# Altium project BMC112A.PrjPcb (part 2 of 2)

## Sheet BMC112A_Power.SchDoc: LM5171 EVM Power Stage
size 431 x 279 mm; Date: Not shown in title block; ApprovedBy: Not shown in title block; CheckedBy: Not shown in title block; Author: Not shown in title block; CompanyName: Not shown in title block; Engineer: Not shown in title block; Organization: Not shown in title block; Address1: Not shown in title block; Address2: Not shown in title block; Address3: Not shown in title block; Address4: Not shown in title block; DocumentNumber: 3; Revision: Use project parameter SCH_Rev; SheetNumber: 6; SheetTotal: 8; PageSetup: Record=PageOptions¦CenterHorizontal=True¦CenterVertical=True¦PrintScale=1.00¦XCorrection=1.00¦YCorrection=1.00¦PrintKind=0¦BorderSize=5000000¦LeftOffset=0¦BottomOffset=0¦Orientation=2¦PaperLength=1000¦PaperWidth=1000¦Scale=100¦PaperSource=15¦PrintQuality=600¦MediaType=1¦DitherType=10¦PaperKind=Letter¦PrintScaleMode=1
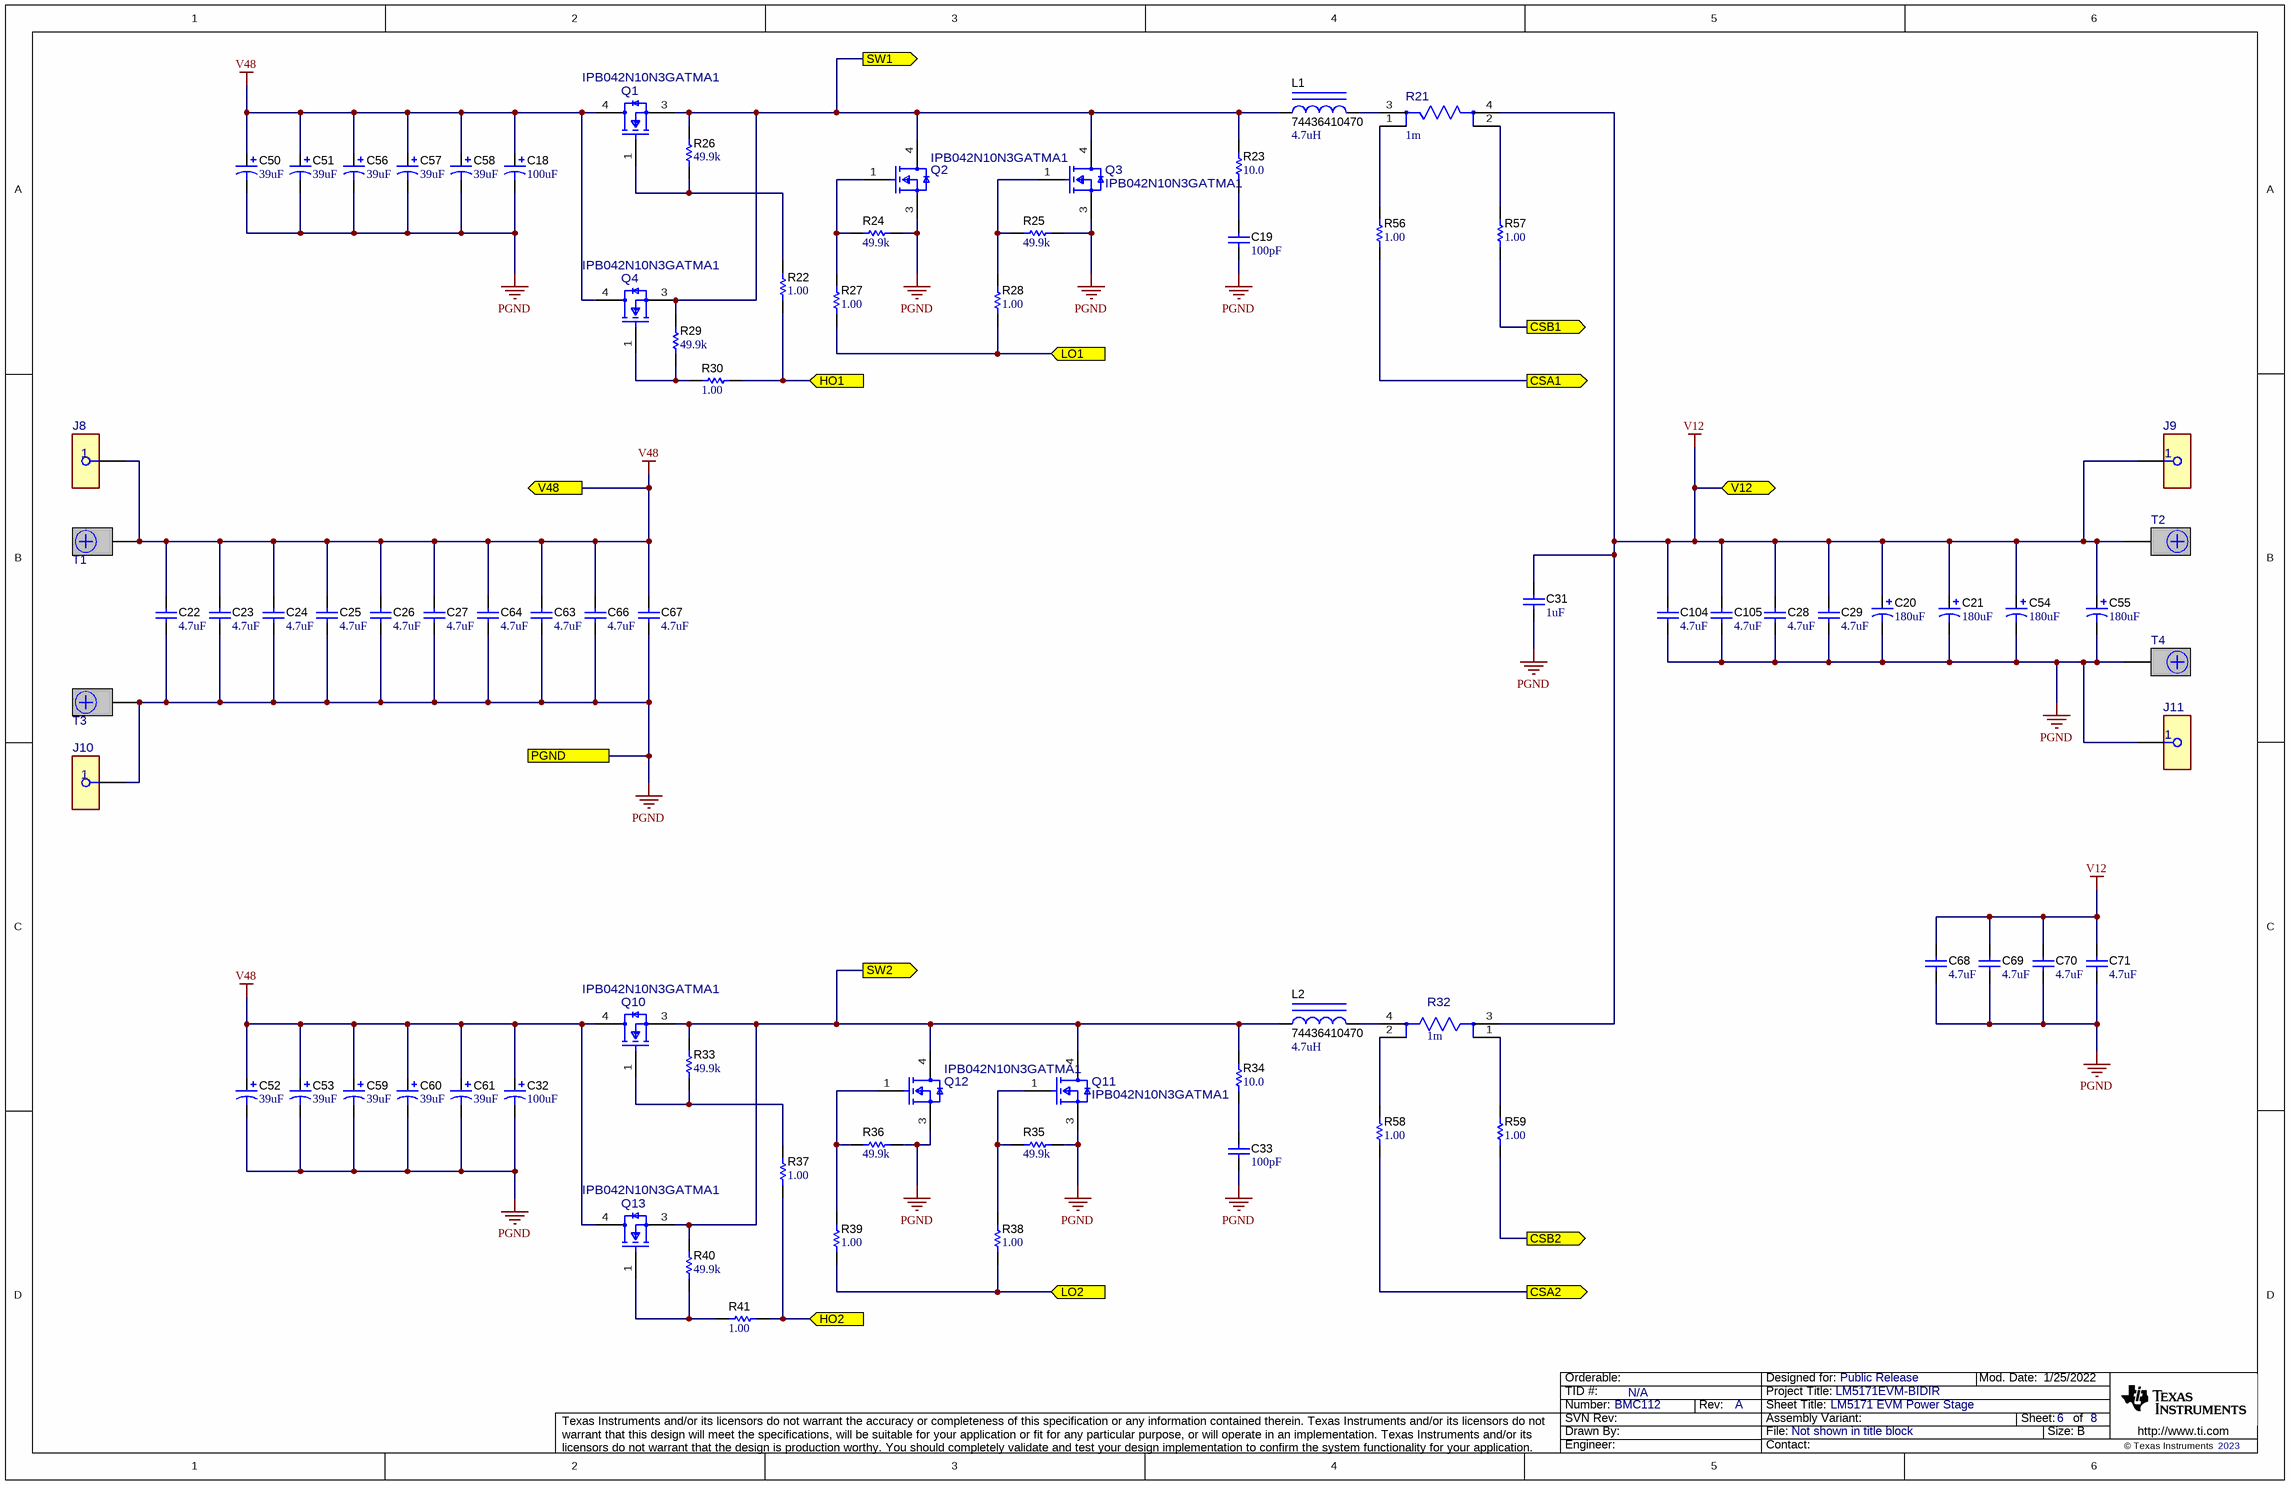
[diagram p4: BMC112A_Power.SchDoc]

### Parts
C18  ValueDisplayed: 100uF  [CAPSMT_62_LH0]  (hidden comment: EMVH101GDA101MLH0S)
C19  ValueDisplayed: 100pF  [0805L]  (hidden comment: 08051A101KAT2A)
C20  ValueDisplayed: 180uF  [CR_1000x1270]  (hidden comment: PCR1H181MCL1GS)
C21  ValueDisplayed: 180uF  [CR_1000x1270]  (hidden comment: PCR1H181MCL1GS)
C22  ValueDisplayed: 4.7uF  [2220_280]  (hidden comment: C5750X7R2A475M230KA)
C23  ValueDisplayed: 4.7uF  [2220_280]  (hidden comment: C5750X7R2A475M230KA)
C24  ValueDisplayed: 4.7uF  [2220_280]  (hidden comment: C5750X7R2A475M230KA)
C25  ValueDisplayed: 4.7uF  [2220_280]  (hidden comment: C5750X7R2A475M230KA)
C26  ValueDisplayed: 4.7uF  [2220_280]  (hidden comment: C5750X7R2A475M230KA)
C27  ValueDisplayed: 4.7uF  [2220_280]  (hidden comment: C5750X7R2A475M230KA)
C28  ValueDisplayed: 4.7uF  [2220_280]  (hidden comment: C5750X7R2A475M230KA)
C29  ValueDisplayed: 4.7uF  [2220_280]  (hidden comment: C5750X7R2A475M230KA)
C31  ValueDisplayed: 1uF  [1206_180]  (hidden comment: GRM31CR72A105KA01L)
C32  ValueDisplayed: 100uF  [CAPSMT_62_LH0]  (hidden comment: EMVH101GDA101MLH0S)
C33  ValueDisplayed: 100pF  [0805L]  (hidden comment: 08051A101KAT2A)
C50  ValueDisplayed: 39uF  [HXA_JA0]  (hidden comment: HHXA800ARA390MJA0G)
C51  ValueDisplayed: 39uF  [HXA_JA0]  (hidden comment: HHXA800ARA390MJA0G)
C52  ValueDisplayed: 39uF  [HXA_JA0]  (hidden comment: HHXA800ARA390MJA0G)
C53  ValueDisplayed: 39uF  [HXA_JA0]  (hidden comment: HHXA800ARA390MJA0G)
C54  ValueDisplayed: 180uF  [CR_1000x1270]  (hidden comment: PCR1H181MCL1GS)
C55  ValueDisplayed: 180uF  [CR_1000x1270]  (hidden comment: PCR1H181MCL1GS)
C56  ValueDisplayed: 39uF  [HXA_JA0]  (hidden comment: HHXA800ARA390MJA0G)
C57  ValueDisplayed: 39uF  [HXA_JA0]  (hidden comment: HHXA800ARA390MJA0G)
C58  ValueDisplayed: 39uF  [HXA_JA0]  (hidden comment: HHXA800ARA390MJA0G)
C59  ValueDisplayed: 39uF  [HXA_JA0]  (hidden comment: HHXA800ARA390MJA0G)
C60  ValueDisplayed: 39uF  [HXA_JA0]  (hidden comment: HHXA800ARA390MJA0G)
C61  ValueDisplayed: 39uF  [HXA_JA0]  (hidden comment: HHXA800ARA390MJA0G)
C63  ValueDisplayed: 4.7uF  [2220_280]  (hidden comment: C5750X7R2A475M230KA)
C64  ValueDisplayed: 4.7uF  [2220_280]  (hidden comment: C5750X7R2A475M230KA)
C66  ValueDisplayed: 4.7uF  [2220_280]  (hidden comment: C5750X7R2A475M230KA)
C67  ValueDisplayed: 4.7uF  [2220_280]  (hidden comment: C5750X7R2A475M230KA)
C68  ValueDisplayed: 4.7uF  [2220_280]  (hidden comment: C5750X7R2A475M230KA)
C69  ValueDisplayed: 4.7uF  [2220_280]  (hidden comment: C5750X7R2A475M230KA)
C70  ValueDisplayed: 4.7uF  [2220_280]  (hidden comment: C5750X7R2A475M230KA)
C71  ValueDisplayed: 4.7uF  [2220_280]  (hidden comment: C5750X7R2A475M230KA)
C104  ValueDisplayed: 4.7uF  [2220_280]  (hidden comment: C5750X7R2A475M230KA)
C105  ValueDisplayed: 4.7uF  [2220_280]  (hidden comment: C5750X7R2A475M230KA)
J8  6095  [FP-6095_CONN_JACK-MFG]  (value not drawn)
J9  6095  [FP-6095_CONN_JACK-MFG]  (value not drawn)
J10  6095  [FP-6095_CONN_JACK-MFG]  (value not drawn)
J11  6095  [FP-6095_CONN_JACK-MFG]  (value not drawn)
L1  74436410470  value 4.7uH  [WE-HCF_2818]
L2  74436410470  value 4.7uH  [WE-HCF_2818]
Q1  IPB042N10N3GATMA1  [FP-IPB042N10N3GATMA1_D2PAK-MFG]
Q2  IPB042N10N3GATMA1  [FP-IPB042N10N3GATMA1_D2PAK-MFG]
Q3  IPB042N10N3GATMA1  [FP-IPB042N10N3GATMA1_D2PAK-MFG]
Q4  IPB042N10N3GATMA1  [FP-IPB042N10N3GATMA1_D2PAK-MFG]
Q10  IPB042N10N3GATMA1  [FP-IPB042N10N3GATMA1_D2PAK-MFG]
Q11  IPB042N10N3GATMA1  [FP-IPB042N10N3GATMA1_D2PAK-MFG]
Q12  IPB042N10N3GATMA1  [FP-IPB042N10N3GATMA1_D2PAK-MFG]
Q13  IPB042N10N3GATMA1  [FP-IPB042N10N3GATMA1_D2PAK-MFG]
R21  value 1m  [FP-FC4L90R001GER_1835-MFG]  (hidden comment: FC4L90R001GER)
R22  ValueDisplayed: 1.00  [0805L]  (hidden comment: CRCW08051R00FKEA)
R23  ValueDisplayed: 10.0  [1218]  (hidden comment: CRCW121810R0FKEK)
R24  ValueDisplayed: 49.9k  [0805L]  (hidden comment: CRCW080549K9FKEA)
R25  ValueDisplayed: 49.9k  [0805L]  (hidden comment: CRCW080549K9FKEA)
R26  ValueDisplayed: 49.9k  [0805L]  (hidden comment: CRCW080549K9FKEA)
R27  ValueDisplayed: 1.00  [0805L]  (hidden comment: CRCW08051R00FKEA)
R28  ValueDisplayed: 1.00  [0805L]  (hidden comment: CRCW08051R00FKEA)
R29  ValueDisplayed: 49.9k  [0805L]  (hidden comment: CRCW080549K9FKEA)
R30  ValueDisplayed: 1.00  [0805L]  (hidden comment: CRCW08051R00FKEA)
R32  value 1m  [FP-FC4L90R001GER_1835-MFG]  (hidden comment: FC4L90R001GER)
R33  ValueDisplayed: 49.9k  [0805L]  (hidden comment: CRCW080549K9FKEA)
R34  ValueDisplayed: 10.0  [1218]  (hidden comment: CRCW121810R0FKEK)
R35  ValueDisplayed: 49.9k  [0805L]  (hidden comment: CRCW080549K9FKEA)
R36  ValueDisplayed: 49.9k  [0805L]  (hidden comment: CRCW080549K9FKEA)
R37  ValueDisplayed: 1.00  [0805L]  (hidden comment: CRCW08051R00FKEA)
R38  ValueDisplayed: 1.00  [0805L]  (hidden comment: CRCW08051R00FKEA)
R39  ValueDisplayed: 1.00  [0805L]  (hidden comment: CRCW08051R00FKEA)
R40  ValueDisplayed: 49.9k  [0805L]  (hidden comment: CRCW080549K9FKEA)
R41  ValueDisplayed: 1.00  [0805L]  (hidden comment: CRCW08051R00FKEA)
R56  ValueDisplayed: 1.00  [0603L]  (hidden comment: CRCW06031R00FKEA)
R57  ValueDisplayed: 1.00  [0603L]  (hidden comment: CRCW06031R00FKEA)
R58  ValueDisplayed: 1.00  [0603L]  (hidden comment: CRCW06031R00FKEA)
R59  ValueDisplayed: 1.00  [0603L]  (hidden comment: CRCW06031R00FKEA)
T1  CXS70-14-C  [Panduit_CXS70-14-C]  (value not drawn)
T2  CXS70-14-C  [Panduit_CXS70-14-C]  (value not drawn)
T3  CXS70-14-C  [Panduit_CXS70-14-C]  (value not drawn)
T4  CXS70-14-C  [Panduit_CXS70-14-C]  (value not drawn)

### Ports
CSA1 (out), CSA2 (out), CSB1 (out), CSB2 (out), HO1 (in), HO2 (in), LO1 (in), LO2 (in), PGND, SW1 (out), SW2 (out), V12 (bidir), V48 (out)

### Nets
PGND: C18.2(-) C19.2 C20.2(-) C21.2(-) C22.2 C23.2 C24.2 C25.2 C26.2 C27.2 C28.2 C29.2 C31.1 C32.2(-) C33.2 C50.2(-) C51.2(-) C52.2(-) C53.2(-) C54.2(-) C55.2(-) C56.2(-) C57.2(-) C58.2(-) C59.2(-) C60.2(-) C61.2(-) C63.2 C64.2 C66.2 C67.2 C68.2 C69.2 C70.2 C71.2 C104.2 C105.2 J10.1 J11.1 Q2.3(SOURCE) Q3.3(SOURCE) Q11.3(SOURCE) Q12.3(SOURCE) R24.2 R25.2 R35.2 R36.2 T3.1 T4.1 ; port PGND
V12: C20.1(+) C21.1(+) C28.1 C29.1 C31.2 C54.1(+) C55.1(+) C68.1 C69.1 C70.1 C71.1 C104.1 C105.1 J9.1 R21.4(2_I) R32.3(1_I) T2.1 ; port V12
V48: C18.1(+) C22.1 C23.1 C24.1 C25.1 C26.1 C27.1 C32.1(+) C50.1(+) C51.1(+) C52.1(+) C53.1(+) C56.1(+) C57.1(+) C58.1(+) C59.1(+) C60.1(+) C61.1(+) C63.1 C64.1 C66.1 C67.1 J8.1 Q1.4(DRAIN) Q4.4(DRAIN) Q10.4(DRAIN) Q13.4(DRAIN) T1.1 ; port V48
CSA1: R56.1 ; port CSA1
CSA2: R58.1 ; port CSA2
CSB1: R57.1 ; port CSB1
CSB2: R59.1 ; port CSB2
HO1: R22.1 R30.1 ; port HO1
HO2: R37.1 R41.1 ; port HO2
LO1: R27.1 R28.1 ; port LO1
LO2: R38.1 R39.1 ; port LO2
SW1: L1.1 Q1.3(SOURCE) Q2.4(DRAIN) Q3.4(DRAIN) Q4.3(SOURCE) R23.2 R26.1 R29.1 ; port SW1
SW2: L2.2 Q10.3(SOURCE) Q11.4(DRAIN) Q12.4(DRAIN) Q13.3(SOURCE) R33.2 R34.2 R40.2 ; port SW2
NetC19_1: C19.1 R23.1
NetC33_1: C33.1 R34.1
NetL1_2: L1.2 R21.3(1_I)
NetL2_1: L2.1 R32.4(2_I)
NetQ1_1: Q1.1(GATE) R22.2 R26.2
NetQ2_1: Q2.1(GATE) R24.1 R27.2
NetQ3_1: Q3.1(GATE) R25.1 R28.2
NetQ4_1: Q4.1(GATE) R29.2 R30.2
NetQ10_1: Q10.1(GATE) R33.1 R37.2
NetQ11_1: Q11.1(GATE) R35.1 R38.2
NetQ12_1: Q12.1(GATE) R36.1 R39.2
NetQ13_1: Q13.1(GATE) R40.1 R41.2
NetR21_1: R21.1(1_V) R56.2
NetR21_2: R21.2(2_V) R57.2
NetR32_1: R32.1(1_V) R59.2
NetR32_2: R32.2(2_V) R58.2

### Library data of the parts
C18 C32 = CMP-0011313-2: CAP, AL, 100 uF, 100 V, +/- 20%, 0.24 ohm, SMD; Manufacturer: Chemi-Con; Polarized: Y; CompType: Capacitor; Value: 100uF; U/M: EA; Cap_F: 100µF; VDC_V: 100V; ESR_ohm: 0.24; IRMS_A: 650mA; TaMin_C: -40°C; TaMax_C: 125°C; Cap_Case: LH0; AEC Category: Q200; SizeArea_mm2: 289; SizeAreaWB_mm2: 361; SizeX_mm: 17; SizeZ_mm: 16.5
C19 C33 = CMP-0007518-2: CAP, CERM, 100 pF, 100 V, +/- 10%, C0G/NP0, 0805; Manufacturer: AVX; Polarized: N; Value: 100pF; U/M: EA; ESR_ohm: 0.356; Value1: 0.356 ohm; VDC_V: 100V; TaMin_C: -55°C; TaMax_C: 125°C; Cap_Case: 0805; AEC Category: Q200; SizeArea_mm2: 2.5; SizeAreaWB_mm2: 6.75; SizeX_mm: 2; SizeY_mm: 1.25; SizeZ_mm: 1.45
C20 C21 C54 C55 = CMP-0012273-3: CAP, Aluminum Polymer, 180 uF, 50 V, +/- 20%, 0.019 ohm, SMD, 2-Leads, Dia 10.5mm, Pin Spacing 8mm SMD; Manufacturer: Nichicon; Polarized: Y; CompType: Capacitor; Value: 180uF; Cap_F: 180µF; VDC_V: 50V; ESR_ohm: 19m; IRMS_A: 3.5A; TaMin_C: -55°C; TaMax_C: 125°C; Cap_Case: 10x12.7mm; AEC Category: Q200; AEC Qualified: N
C22-C29 C63 C64 C66-C71 C104 C105 = CMP-0009385-2: CAP, CERM, 4.7 uF, 100 V, +/- 20%, X7R, 2220; Manufacturer: TDK; Polarized: N; Value: 4.7uF; U/M: EA; Cap_F: 4.7µF; ESR_ohm: 1.5m; Value1: 0.0015 ohm; VDC_V: 100V; IRMS_A: 5.5A; TaMin_C: -55°C; TaMax_C: 125°C; Cap_Case: 2220; AEC Category: Q200; SizeArea_mm2: 28.5; SizeAreaWB_mm2: 53.9; SizeX_mm: 5.7; SizeY_mm: 5; SizeZ_mm: 2.8
C31 = CMP-0008970-2: CAP, CERM, 1 uF, 100 V, +/- 10%, X7R, 1206; Manufacturer: MuRata; Polarized: N; Value: 1uF; U/M: EA; Cap_F: 1µF; Value1: Unknown; VDC_V: 100V; TaMin_C: -55°C; TaMax_C: 125°C; Cap_Case: 2220; SizeArea_mm2: 5.12; SizeAreaWB_mm2: 10.92; SizeX_mm: 3.2; SizeY_mm: 1.6; SizeZ_mm: 1.8; AEC Category: Q200
C50-C53 C56-C61 = CMP-0012265-3: CAP, Aluminum Polymer, 39 uF, 80 V, +/- 20%, 0.035 ohm, AEC-Q200 Grade 1, D10xL10mm SMD; Manufacturer: Chemi-Con; CompType: Capacitor; ESR_ohm: 35m; VDC_V: 80V; Value: 39uF; Polarized: Y; Cap_F: 39µF; IRMS_A: 1.2A; TaMin_C: -55°C; TaMax_C: 125°C; Cap_Case: 10X10mm; AEC Category: Q200; AEC Grade: 1
J8-J11 = CMP-0097398-1: Banana Jack Connector Standard Banana Solder Lug; Manufacturer: Keystone Electronics; AEC Qualified: No; ContactFinish: Tin; Is Female: yes; Conn Orientation: Vertical
L1 L2 = CMP-0064062-1: Inductor, Shielded, Ferrite, 4.7 uH, 32 A, 0.0015 ohm, SMD; Manufacturer: Wurth Elektronik; AEC Category: Q200; AEC Qualified: N; DCR_ohm: 1.5m; Green_Lifecycle: Not Set; Green_REACh: Incomplete; Imax_A: 32A; Ind_H: 4.7µH; Irms: 32A @ 50C rise; Isat: 45A @ 20% inductance drop; SizeArea_mm2: 555.75; SizeAreaWB_mm2: 655.75; SizeX_mm: 28.5; SizeY_mm: 19.5; SizeZ_mm: 18.5
Q1-Q4 Q10-Q13 = CMP-0087591-1: N-Channel 100V 100A (Tc) 214W (Tc) Surface Mount D²PAK (TO-263AB); Manufacturer: Infineon; Transconductance: 145S; Turn Off Delay Time: 48ns; IdsMax_A: 137A; TJmax_C: +175°C; Pulse Drain Current: 548A; Threshold Vgs Max: 3.5V; Rdson45_ohm: 3.6mΩ; Typ Forward Diode Voltage: 1V; Standoff Height: 0mm; QgTyp_nC: 88nC @ 10V; Reverse Recovery Time: 68ns; Import Ts: 1521842123; SizeZ_mm: 4.7mm; Input Capacitace At Vds: 6320pF @ 50V; Rthja Max: 62K/W; Threshold Vgs Min: 2V; Reverse Recovery Charge: 135nC; Number Of Channels: 1; Ciiva Ids: 4154385; ChMode: False; AEC Qualified: No; Max Forward Diode Voltage: 1.2V; Turn On Delay Time: 27ns; Vgs_V: 20V
R21 R32 = CMP-0001578-1: 1 mOhms ±2% 4W Chip Resistor Wide 3518 (9045 Metric), 1835 Current Sense, Moisture Resistant Metal Foil; Manufacturer: Ohmite; AEC Qualified: No; SizeZ_mm: 0.8mm; TempCo: 100ppm/°C
R22 R27 R28 R30 R37-R39 R41 = CMP-0021009-3: RES, 1.00, 1%, 0.125 W, AEC-Q200 Grade 0, 0805; Manufacturer: Vishay-Dale; Value: 1.00; Res_ohm: 1; Value_Code: 1R00; Power_W: 125mW; Value2: 0.125W; VDC_V: 150V; TempCo: 100 ppm/C; EIA_Code: E96; AEC Category: Q200; AEC Grade: 0; AEC Qualified: Y; SizeArea_mm2: 2.5; SizeX_mm: 2; SizeY_mm: 1.25; SizeZ_mm: 1.45
R23 R34 = CMP-0015024-3: RES, 10.0, 1%, 1 W, AEC-Q200 Grade 0, 1218; Manufacturer: Vishay-Dale; Value: 10.0; Res_ohm: 10; Value_Code: 10R0; Power_W: 1W; VDC_V: 200V; TempCo: 100 ppm/C; EIA_Code: E96; AEC Category: Q200; AEC Grade: 0; AEC Qualified: Y; SizeArea_mm2: 14.72; SizeAreaWB_mm2: 23.52; SizeX_mm: 3.2; SizeY_mm: 4.6; SizeZ_mm: 0.6
R24-R26 R29 R33 R35 R36 R40 = CMP-0021283-3: RES, 49.9 k, 1%, 0.125 W, AEC-Q200 Grade 0, 0805; Manufacturer: Vishay-Dale; Value: 49.9k; Value_Code: 49k9; Power_W: 125mW; Value2: 0.125W; VDC_V: 150V; TempCo: 100 ppm/C; EIA_Code: E96; AEC Category: Q200; AEC Grade: 0; AEC Qualified: Y; SizeArea_mm2: 2.5; SizeX_mm: 2; SizeY_mm: 1.25; SizeZ_mm: 1.45
R56-R59 = CMP-0022170-4: RES, 1.00, 1%, 0.1 W, AEC-Q200 Grade 0, 0603; Manufacturer: Vishay-Dale; Value: 1.00; Res_ohm: 1; Value_Code: 1R00; Power_W: 100mW; Value2: 0.1W; VDC_V: 75V; TempCo: 100 ppm/C; EIA_Code: E96; AEC Category: Q200; AEC Qualified: Y; AEC Grade: 0; SizeArea_mm2: 1.28; SizeX_mm: 1.6; SizeY_mm: 0.8
T1-T4 = CMP-0075010-2: Terminal 70A Lug; Manufacturer: Panduit; CompType: Screw Terminal; CNHeader: False; Green_Lifecycle: Not Set; Green_REACh: Incomplete

## Sheet BMC112A_Interface.SchDoc: LM5171 EVM Interface Schematic
size 431 x 279 mm; Date: Not shown in title block; ApprovedBy: Not shown in title block; CheckedBy: Not shown in title block; Author: Not shown in title block; CompanyName: Not shown in title block; Engineer: Not shown in title block; Organization: Not shown in title block; Address1: Not shown in title block; Address2: Not shown in title block; Address3: Not shown in title block; Address4: Not shown in title block; DocumentNumber: 4; Revision: Use project parameter SCH_Rev; SheetNumber: 7; SheetTotal: 8; PageSetup: Record=PageOptions¦CenterHorizontal=True¦CenterVertical=True¦PrintScale=1.00¦XCorrection=1.00¦YCorrection=1.00¦PrintKind=0¦BorderSize=5000000¦LeftOffset=0¦BottomOffset=0¦Orientation=2¦PaperLength=1000¦PaperWidth=1000¦Scale=100¦PaperSource=15¦PrintQuality=600¦MediaType=1¦DitherType=10¦PaperKind=Letter¦PrintScaleMode=1
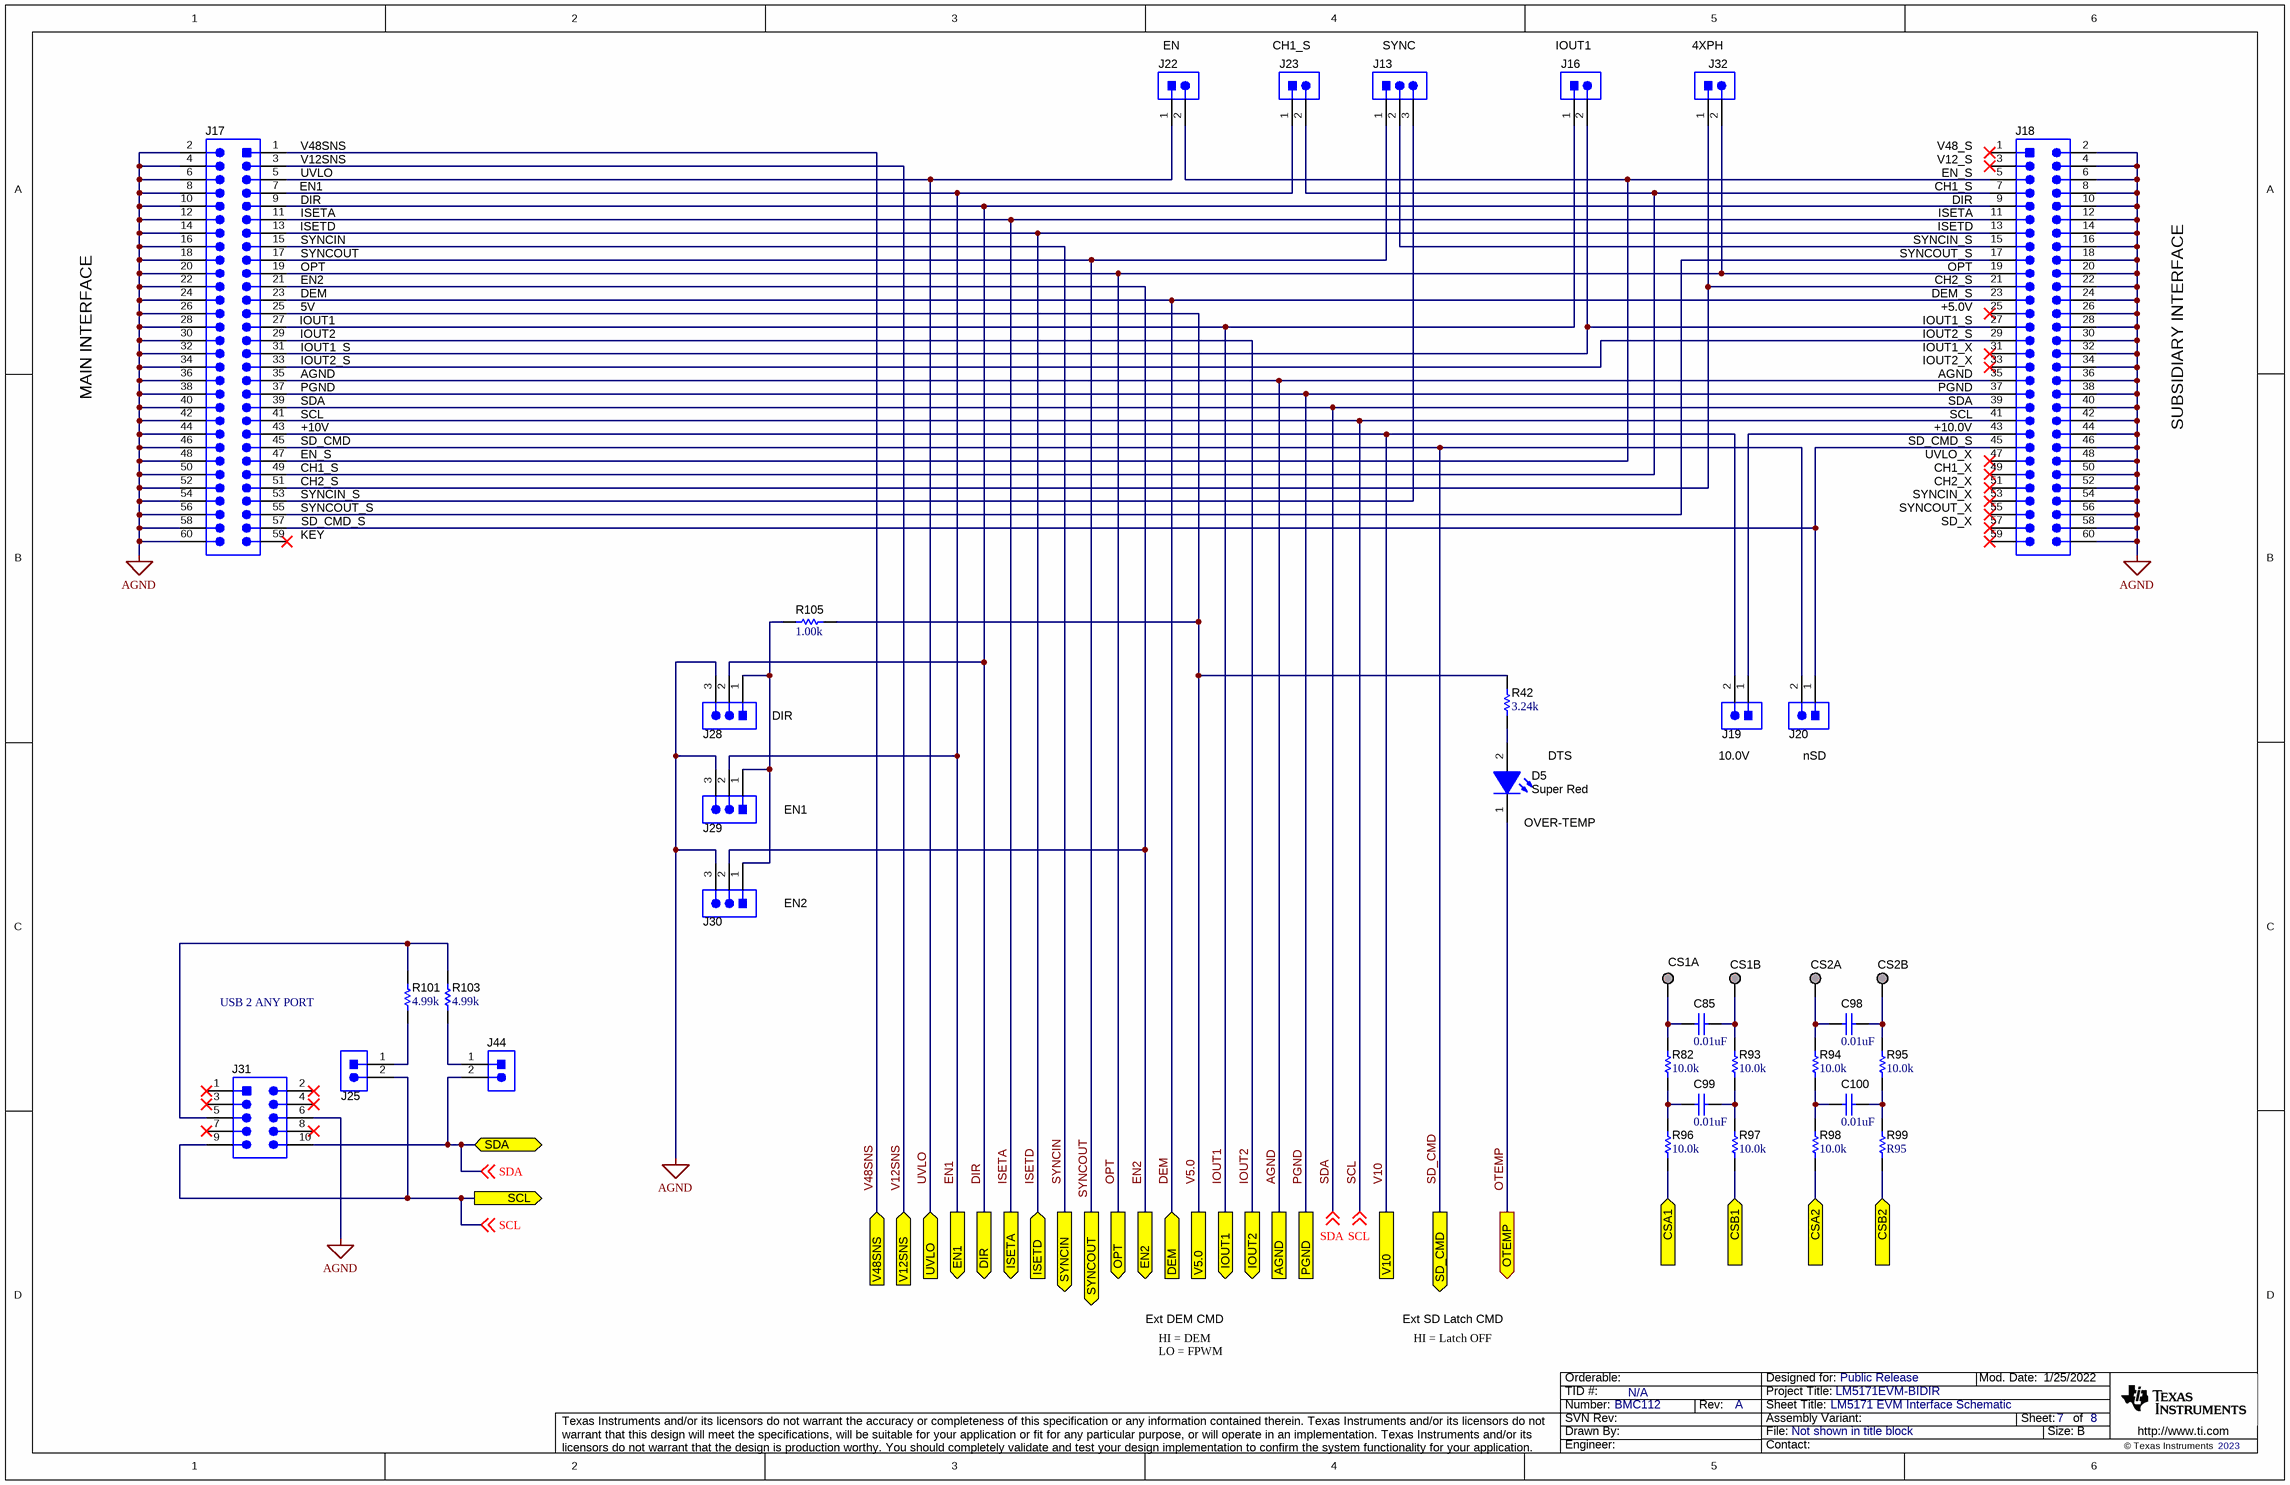
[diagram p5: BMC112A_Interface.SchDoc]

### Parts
C85  ValueDisplayed: 0.01uF  [0603L]  (hidden comment: 06031C103KAT2A)
C98  ValueDisplayed: 0.01uF  [0603L]  (hidden comment: 06031C103KAT2A)
C99  ValueDisplayed: 0.01uF  [0603L]  (hidden comment: 06031C103KAT2A)
C100  ValueDisplayed: 0.01uF  [0603L]  (hidden comment: 06031C103KAT2A)
CS1A  S2751-46R  [Harwin_S2751-46R]  (value not drawn)  (no BOM)
CS1B  S2751-46R  [Harwin_S2751-46R]  (value not drawn)  (no BOM)
CS2A  S2751-46R  [Harwin_S2751-46R]  (value not drawn)  (no BOM)
CS2B  S2751-46R  [Harwin_S2751-46R]  (value not drawn)  (no BOM)
D5  value Super Red  [WL-SMCW_RED]  (hidden comment: 150060SS75000)
J13  61300311121  [WURTH_61300311121]  (value not drawn)
J16  61300211121  [WURTH_61300211121]  (value not drawn)
J17  HMTSW-130-07-G-D-240  [SAMTEC_HMTSW-130-07-G-D-240]  (value not drawn)
J18  HMTSW-130-07-G-D-240  [SAMTEC_HMTSW-130-07-G-D-240]  (value not drawn)
J19  61300211121  [WURTH_61300211121]  (value not drawn)
J20  61300211121  [WURTH_61300211121]  (value not drawn)
J22  61300211121  [WURTH_61300211121]  (value not drawn)
J23  61300211121  [WURTH_61300211121]  (value not drawn)
J25  61300211121  [WURTH_61300211121]  (value not drawn)
J28  61300311121  [WURTH_61300311121]  (value not drawn)
J29  61300311121  [WURTH_61300311121]  (value not drawn)
J30  61300311121  [WURTH_61300311121]  (value not drawn)
J31  N2510-6002-RB  [CONN_2510-6002]  (value not drawn)
J32  61300211121  [WURTH_61300211121]  (value not drawn)
J44  61300211121  [WURTH_61300211121]  (value not drawn)
R42  ValueDisplayed: 3.24k  [0603L]  (hidden comment: CRCW06033K24FKEA)
R82  ValueDisplayed: 10.0k  [0603L]  (hidden comment: CRCW060310K0FKEA)
R93  ValueDisplayed: 10.0k  [0603L]  (hidden comment: CRCW060310K0FKEA)
R94  ValueDisplayed: 10.0k  [0603L]  (hidden comment: CRCW060310K0FKEA)
R95  ValueDisplayed: 10.0k  [0603L]  (hidden comment: CRCW060310K0FKEA)
R96  ValueDisplayed: 10.0k  [0603L]  (hidden comment: CRCW060310K0FKEA)
R97  ValueDisplayed: 10.0k  [0603L]  (hidden comment: CRCW060310K0FKEA)
R98  ValueDisplayed: 10.0k  [0603L]  (hidden comment: CRCW060310K0FKEA)
R99  ValueDisplayed: R95  [0603L]  (hidden comment: CRCW060310K0FKEA)
R101  ValueDisplayed: 4.99k  [0603]  (hidden comment: CRCW06034K99FKEAC)
R103  ValueDisplayed: 4.99k  [0603]  (hidden comment: CRCW06034K99FKEAC)
R105  ValueDisplayed: 1.00k  [0603]  (hidden comment: RC0603FR-071KL)

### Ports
AGND, CSA1 (in), CSA2 (in), CSB1 (in), CSB2 (in), DEM (in), DIR (out), EN1 (out), EN2 (out), IOUT1 (out), IOUT2 (out), ISETA (out), ISETD (in), OPT (out), OTEMP (out), PGND, SCL (out), SD_CMD (out), SDA (bidir), SYNCIN (out), SYNCOUT (out), UVLO (in), V5.0, V10, V12SNS (in), V48SNS (in)

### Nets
AGND: J17.2 J17.4 J17.6 J17.8 J17.10 J17.12 J17.14 J17.16 J17.18 J17.20 J17.22 J17.24 J17.26 J17.28 J17.30 J17.32 J17.34 J17.35 J17.36 J17.38 J17.40 J17.42 J17.44 J17.46 J17.48 J17.50 J17.52 J17.54 J17.56 J17.58 J17.60 J18.2 J18.4 J18.6 J18.8 J18.10 J18.12 J18.14 J18.16 J18.18 J18.20 J18.22 J18.24 J18.26 J18.28 J18.30 J18.32 J18.34 J18.35 J18.36 J18.38 J18.40 J18.42 J18.44 J18.46 J18.48 J18.50 J18.52 J18.54 J18.56 J18.58 J18.60 J28.3 J29.3 J30.3 J31.6 ; port AGND
PGND: J17.37 J18.37 ; port PGND
V5.0: J17.25 R42.2 R105.2 ; port V5.0
V10: J17.43 J19.2 ; port V10
CSA1: R96.1 ; port CSA1
CSA2: R98.1 ; port CSA2
CSB1: R97.1 ; port CSB1
CSB2: R99.1 ; port CSB2
DEM: J17.23 J18.23 ; port DEM
DIR: J17.9 J18.9 J28.2 ; port DIR
EN1: J17.7 J23.1 J29.2 ; port EN1
EN2: J17.21 J30.2 ; port EN2
IOUT1: J16.1 J17.27 ; port IOUT1
IOUT2: J17.29 ; port IOUT2
ISETA: J17.11 J18.11 ; port ISETA
ISETD: J17.13 J18.13 ; port ISETD
OPT: J17.19 J18.19 J32.2 ; port OPT
OTEMP: D5.1(K) ; port OTEMP
SCL: J17.41 J18.41 J25.2 J31.9 ; off-sheet SCL, port SCL
SD_CMD: J17.45 J20.2 ; port SD_CMD
SDA: J17.39 J18.39 J31.10 J44.2 ; off-sheet SDA, port SDA
SYNCIN: J17.15 ; port SYNCIN
SYNCOUT: J13.1 J17.17 ; port SYNCOUT
UVLO: J17.5 J22.1 ; port UVLO
V12SNS: J17.3 ; port V12SNS
V48SNS: J17.1 ; port V48SNS
NetC85_1: C85.1 CS1B.1 R93.2
NetC85_2: C85.2 CS1A.1 R82.2
NetC98_1: C98.1 CS2B.1 R95.2
NetC98_2: C98.2 CS2A.1 R94.2
NetC99_1: C99.1 R93.1 R97.2
NetC99_2: C99.2 R82.1 R96.2
NetC100_1: C100.1 R95.1 R99.2
NetC100_2: C100.2 R94.1 R98.2
NetD5_2: D5.2(A) R42.1
NetJ13_2: J13.2 J18.15
NetJ13_3: J13.3 J17.53
NetJ16_2: J16.2 J17.31 J18.27
NetJ17_33: J17.33 J18.29
NetJ17_47: J17.47 J18.5 J22.2
NetJ17_49: J17.49 J18.7 J23.2
NetJ17_51: J17.51 J18.21 J32.1
NetJ17_55: J17.55 J18.17
NetJ17_57: J17.57 J18.45 J20.1
NetJ18_43: J18.43 J19.1
NetJ25_1: J25.1 R101.1
NetJ28_1: J28.1 J29.1 J30.1 R105.1
NetJ31_5: J31.5 R101.2 R103.2
NetJ44_1: J44.1 R103.1

Not connected (* = marked no-connect by the designer): J17 59*; J18 1* 3* 25* 31* 33* 47* 49* 51* 53* 55* 57* 59*; J31 1* 2* 3* 4* 7* 8*

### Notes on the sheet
- (near J22) EN
- (near J23) CH1_S
- (near J13) SYNC
- (near J16) IOUT1
- (near J32) 4XPH
- (near J17) UVLO
- (near J17) V48SNS
- (near J17) V12SNS
- (near J18) V48_S
- (near J18) V12_S
- (near J18) EN_S
- (near J17) DIR
- (near J17) EN1
- (near J17) ISETA
- (near J17) ISETD
- (near J18) CH1_S
- (near J18) ISETD
- (near J18) ISETA
- (near J18) DIR
- (near J17) 5V
- (near J17) EN2
- (near J17) OPT
- (near J17) DEM
- (near J17) SYNCIN
- (near J17) SYNCOUT
- (near J18) SYNCOUT_S
- (near J18) SYNCIN_S
- (near J18) DEM_S
- (near J18) CH2_S
- (near J18) +5.0V
- (near J18) OPT
- MAIN INTERFACE
- (near J17) IOUT1
- (near J17) IOUT2
- (near J17) IOUT1_S
- (near J17) IOUT2_S
- (near J18) IOUT1_X
- (near J18) IOUT2_X
- (near J18) IOUT1_S
- (near J18) IOUT2_S
- SUBSIDIARY INTERFACE
- (near J17) SCL
- (near J17) SDA
- (near J17) +10V
- (near J17) AGND
- (near J17) PGND
- (near J17) SD_CMD
- (near J18) SD_CMD_S
- (near J18) +10.0V
- (near J18) AGND
- (near J18) PGND
- (near J18) SDA
- (near J18) SCL
- (near J17) EN_S
- (near J17) CH1_S
- (near J17) CH2_S
- (near J17) SYNCIN_S
- (near J18) SYNCIN_X
- (near J18) UVLO_X
- (near J18) CH1_X
- (near J18) CH2_X
- (near J17) KEY
- (near J17) SD_CMD_S
- (near J17) SYNCOUT_S
- (near J18) SYNCOUT_X
- (near J18) SD_X
- (near J28) DIR
- DTS
- 10.0V
- (near J20) nSD
- (near J29) EN1
- (near D5) OVER-TEMP
- (near J30) EN2
- USB 2 ANY PORT
- HI = DEM   LO = FPWM
- Ext DEM CMD
- HI = Latch OFF
- Ext SD Latch CMD

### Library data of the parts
C85 C98-C100 = CMP-0006727-4: CAP, CERM, 0.01 uF, 100 V, +/- 10%, X7R, 0603; Manufacturer: AVX; Polarized: N; Value: 0.01uF; U/M: EA; Cap_F: 10nF; ESR_ohm: 98m; Value1: 0.098 ohm; VDC_V: 100V; TaMin_C: -55°C; TaMax_C: 125°C; Cap_Case: 0603; AEC Category: Q200; SizeArea_mm2: 1.28; SizeAreaWB_mm2: 4.68; SizeX_mm: 1.6; SizeY_mm: 0.8; SizeZ_mm: 1
CS1A CS1B CS2A CS2B = CMP-0003968-1: Test Point, SMT; Manufacturer: Harwin
D5 = CMP-0002893-1: LED, Super Red, SMD; Manufacturer: Wurth Elektronik; Type: AlInGaP; Vf_V: 1.9V; Io_A: 20mA; Value1: W; U/M: EA
J13 = CMP-0054796-4: Header, 2.54 mm, 3x1, Gold, TH; Manufacturer: Wurth Elektronik; Green_Lifecycle: Active; Green_REACh: Passed; CT: FALSE; CNHeader: TRUE
J16 J19 J20 J22 J23 J32 = CMP-0054794-2: Header, 2.54 mm, 2x1, Gold, TH; Manufacturer: Wurth Elektronik; Cert_UL: Y; Gender: Male; Green_Lifecycle: Active; Green_REACh: Passed; Pitch_mm: 2.54; Row_Count: 1; Shrouded: N
J17 J18 = CMP-0075499-1: Header, 100mil, 30x2, Gold, TH; Manufacturer: Samtec; CNHeader: True; CT: False; Green_Lifecycle: Active; Green_REACh: Passed
J25 J44 = CMP-0054794-2: Header, 2.54 mm, 2x1, Gold, TH; Manufacturer: Wurth Elektronik; Shrouded: N; Gender: Male; Green_REACh: Passed; Pitch_mm: 2.54; Green_Lifecycle: Active; Row_Count: 1; Cert_UL: Y
J28-J30 = CMP-0054796-4: Header, 2.54 mm, 3x1, Gold, TH; Manufacturer: Wurth Elektronik; Green_Lifecycle: Active; Green_REACh: Passed; CNHeader: TRUE; CT: FALSE
J31 = CMP-0055448-2: Header (shrouded), 100mil, 5x2, High-Temperature, Gold, TH; Manufacturer: 3M; Green_Lifecycle: Active; Green_REACh: Passed
R42 = CMP-0022374-4: RES, 3.24 k, 1%, 0.1 W, AEC-Q200 Grade 0, 0603; Manufacturer: Vishay-Dale; Value: 3.24k; Value_Code: 3k24; Power_W: 100mW; Value2: 0.1W; VDC_V: 75V; TempCo: 100 ppm/C; EIA_Code: E96; AEC Category: Q200; AEC Grade: 0; AEC Qualified: Y; SizeArea_mm2: 1.28; SizeX_mm: 1.6; SizeY_mm: 0.8; SizeZ_mm: 1
R82 R93-R99 = CMP-0021998-4: RES, 10.0 k, 1%, 0.1 W, AEC-Q200 Grade 0, 0603; Manufacturer: Vishay-Dale; Value: 10.0k; Res_ohm: 10k; Value_Code: 10k0; Power_W: 100mW; Value2: 0.1W; VDC_V: 75V; TempCo: 100 ppm/C; EIA_Code: E96; AEC Category: Q200; AEC Qualified: Y; AEC Grade: 0; SizeArea_mm2: 1.28; SizeX_mm: 1.6; SizeY_mm: 0.8; SizeZ_mm: 1
R101 R103 = CMP-0082533-1: RES, 4.99 k, 1%, 0.1 W, 0603; Manufacturer: Vishay-Dale; Power_W: 100mW; TempCo: 100 ppm/C; SizeAreaWB_mm2: 4.68; Value_Code: 4k99; Value: 4.99k; EIA_Code: E96; SizeX_mm: 1.6; SizeY_mm: 0.8; SizeZ_mm: 1; Value2: 0.1W; SizeArea_mm2: 1.28; AEC Qualified: N; VDC_V: 75V; AEC Category: Q200
R105 = CMP-0022895-5: RES, 1.00 k, 1%, 0.1 W, 0603; Manufacturer: Yageo; Power_W: 100mW; TempCo: 100 ppm/C; Value_Code: 1k00; Value: 1.00k; EIA_Code: E96; Res_ohm: 1k; SizeX_mm: 1.6; SizeY_mm: 0.8; SizeZ_mm: 1; Value2: 0.1W; SizeArea_mm2: 1.28; AEC Qualified: N; VDC_V: 75V; AEC Category: Q200; SizeAreaWB_mm2: 4.68

## Sheet BMC112A_Analog.SchDoc: LM5171 EVM Analog Control
size 431 x 279 mm; Date: Not shown in title block; ApprovedBy: Not shown in title block; CheckedBy: Not shown in title block; Author: Not shown in title block; CompanyName: Not shown in title block; Engineer: Not shown in title block; Organization: Not shown in title block; Address1: Not shown in title block; Address2: Not shown in title block; Address3: Not shown in title block; Address4: Not shown in title block; DocumentNumber: 2; Revision: Use project parameter SCH_Rev; SheetNumber: 4; SheetTotal: 8; PageSetup: Record=PageOptions¦CenterHorizontal=True¦CenterVertical=True¦PrintScale=1.00¦XCorrection=1.00¦YCorrection=1.00¦PrintKind=0¦BorderSize=5000000¦LeftOffset=0¦BottomOffset=0¦Orientation=2¦PaperLength=1000¦PaperWidth=1000¦Scale=100¦PaperSource=15¦PrintQuality=600¦MediaType=1¦DitherType=10¦PaperKind=Letter¦PrintScaleMode=1
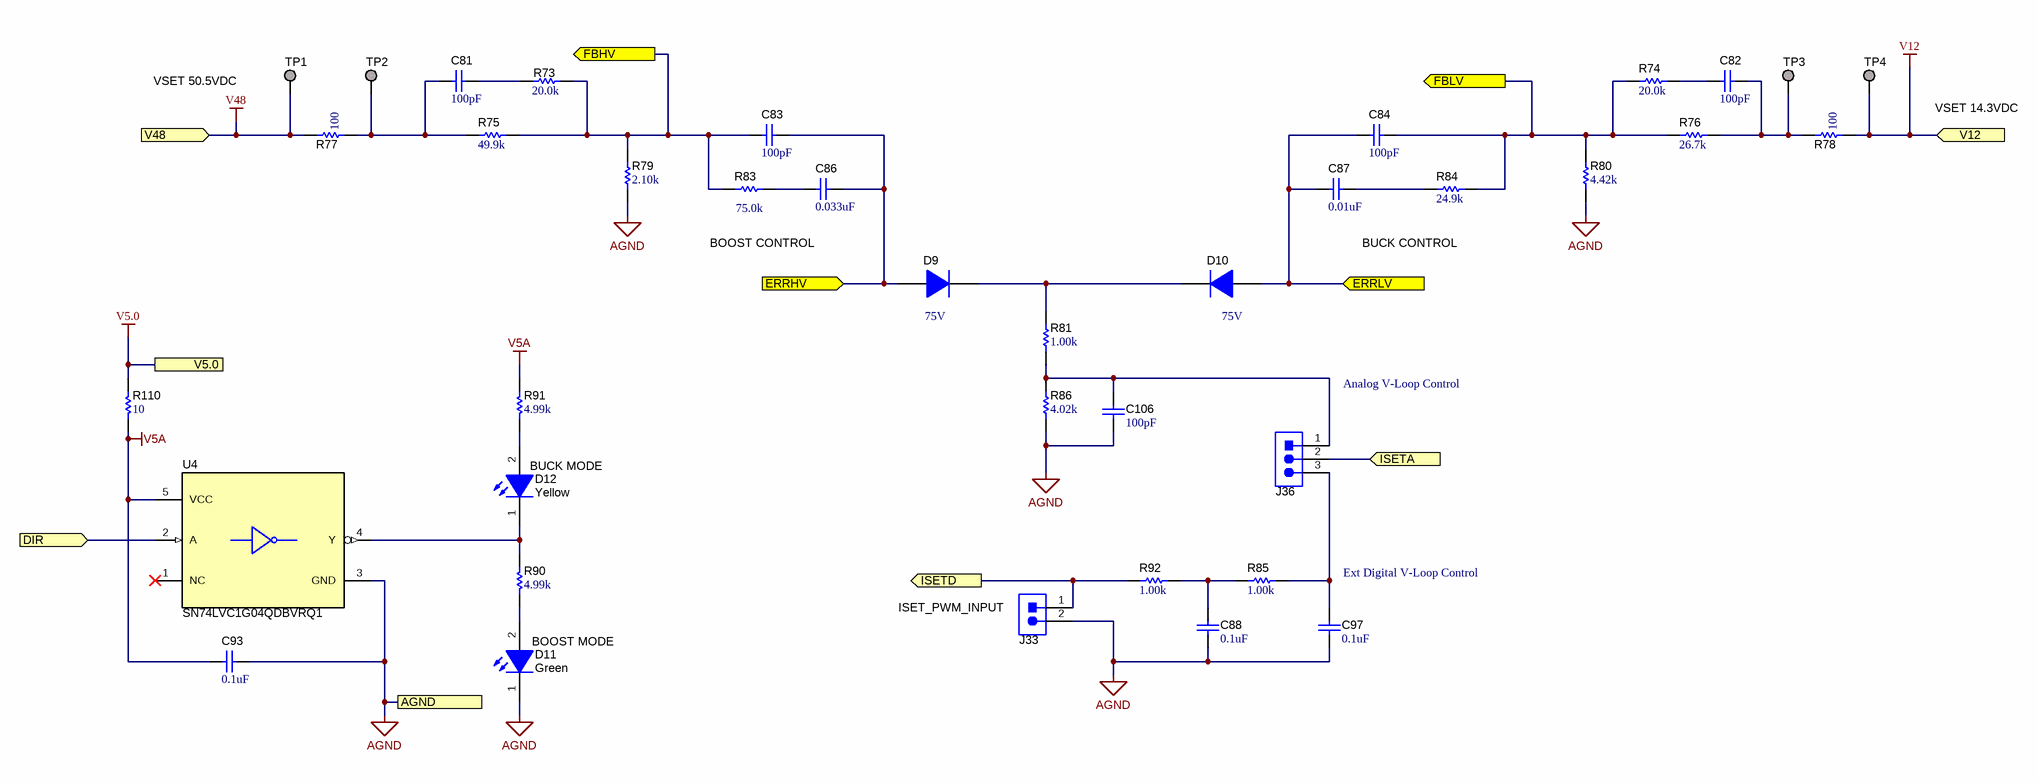
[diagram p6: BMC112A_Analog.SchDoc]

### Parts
C81  ValueDisplayed: 100pF  [0603L]  (hidden comment: C0603C101J5GACTU)
C82  ValueDisplayed: 100pF  [0603L]  (hidden comment: C0603C101J5GACTU)
C83  ValueDisplayed: 100pF  [0603L]  (hidden comment: C0603C101J5GACTU)
C84  ValueDisplayed: 100pF  [0603L]  (hidden comment: C0603C101J5GACTU)
C86  ValueDisplayed: 0.033uF  [0603L]  (hidden comment: CGA3E3X7S2A333K080AB)
C87  ValueDisplayed: 0.01uF  [0603L]  (hidden comment: 06031C103KAT2A)
C88  ValueDisplayed: 0.1uF  [0603L]  (hidden comment: GRM188R72A104KA35D)
C93  ValueDisplayed: 0.1uF  [0603L]  (hidden comment: GRM188R72A104KA35D)
C97  ValueDisplayed: 0.1uF  [0603L]  (hidden comment: GRM188R72A104KA35D)
C106  ValueDisplayed: 100pF  [0603L]  (hidden comment: C0603C101J5GACTU)
D9  value 75V  [SOD-323]  (hidden comment: 1N4448WX-TP)
D10  value 75V  [SOD-323]  (hidden comment: 1N4448WX-TP)
D11  value Green  [WL-SMCW_GREEN]  (hidden comment: 150060VS75000)
D12  value Yellow  [WL-SMCW_YELLOW]  (hidden comment: 150060YS75000)
J33  61300211121  [WURTH_61300211121]  (value not drawn)
J36  61300311121  [WURTH_61300311121]  (value not drawn)
R73  ValueDisplayed: 20.0k  [0603L]  (hidden comment: CRCW060320K0FKEA)
R74  ValueDisplayed: 20.0k  [0603L]  (hidden comment: CRCW060320K0FKEA)
R75  ValueDisplayed: 49.9k  [0805L]  (hidden comment: CRCW080549K9FKEA)
R76  ValueDisplayed: 26.7k  [0805L]  (hidden comment: CRCW080526K7FKEA)
R77  ValueDisplayed: 100  [0603L]  (hidden comment: CRCW0603100RFKEA)
R78  ValueDisplayed: 100  [0603L]  (hidden comment: CRCW0603100RFKEA)
R79  ValueDisplayed: 2.10k  [0603L]  (hidden comment: CRCW06032K10FKEA)
R80  ValueDisplayed: 4.42k  [0603L]  (hidden comment: CRCW06034K42FKEA)
R81  ValueDisplayed: 1.00k  [0603L]  (hidden comment: CRCW06031K00FKEA)
R83  ValueDisplayed: 75.0k  [0603L]  (hidden comment: RC0603FR-0775KL)
R84  ValueDisplayed: 24.9k  [0603L]  (hidden comment: CRCW060324K9FKEA)
R85  ValueDisplayed: 1.00k  [0603L]  (hidden comment: CRCW06031K00FKEA)
R86  ValueDisplayed: 4.02k  [0603L]  (hidden comment: CRCW06034K02FKEA)
R90  ValueDisplayed: 4.99k  [0603L]  (hidden comment: CRCW06034K99FKEA)
R91  ValueDisplayed: 4.99k  [0603L]  (hidden comment: CRCW06034K99FKEA)
R92  ValueDisplayed: 1.00k  [0603L]  (hidden comment: CRCW06031K00FKEA)
R110  ValueDisplayed: 10  [0805_HV1]  (hidden comment: CRCW080510R0JNEA)
TP1  S2761-46R  [Harwin_S2761-46R]  (value not drawn)
TP2  S2761-46R  [Harwin_S2761-46R]  (value not drawn)
TP3  S2761-46R  [Harwin_S2761-46R]  (value not drawn)
TP4  S2761-46R  [Harwin_S2761-46R]  (value not drawn)
U4  SN74LVC1G04QDBVRQ1  [DBV0005A_N]

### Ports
AGND, DIR (in), ERRHV (in), ERRLV (in), FBHV (out), FBLV (out), ISETA (in), ISETD (out), V5.0, V12 (in), V48 (in)

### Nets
AGND: C88.2 C93.1 C97.2 C106.2 D11.1(K) J33.2 R79.2 R80.2 R86.1 U4.3(GND) ; port AGND
V5.0: R110.2 ; port V5.0
V5A: C93.2 R91.1 R110.1 U4.5(VCC)
V12: R78.1 TP4.1 ; port V12
V48: R77.2 TP1.1 ; port V48
DIR: U4.2(A) ; port DIR
ERRHV: C83.1 C86.1 D9.2(A) ; port ERRHV
ERRLV: C84.2 C87.1 D10.2(A) ; port ERRLV
FBHV: C83.2 R73.1 R75.1 R79.1 R83.2 ; port FBHV
FBLV: C84.1 R74.2 R76.2 R80.1 R84.2 ; port FBLV
ISETA: J36.2 ; port ISETA
ISETD: J33.1 R92.1 ; port ISETD
NetC81_1: C81.1 R73.2
NetC81_2: C81.2 R75.2 R77.1 TP2.1
NetC82_1: C82.1 R76.1 R78.2 TP3.1
NetC82_2: C82.2 R74.1
NetC86_2: C86.2 R83.1
NetC87_2: C87.2 R84.1
NetC88_1: C88.1 R85.1 R92.2
NetC97_1: C97.1 J36.3 R85.2
NetC106_1: C106.1 J36.1 R81.1 R86.2
NetD9_1: D9.1(K) D10.1(K) R81.2
NetD11_2: D11.2(A) R90.2
NetD12_1: D12.1(K) R90.1 U4.4(Y)
NetD12_2: D12.2(A) R91.2

Not connected (* = marked no-connect by the designer): U4 1(NC)*

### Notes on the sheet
- VSET 50.5VDC
- VSET 14.3VDC
- BOOST CONTROL
- BUCK CONTROL
- Analog V-Loop Control
- (near D12) BUCK MODE
- (near D11) BOOST MODE
- (near J33) ISET_PWM_INPUT
- Ext Digital V-Loop Control

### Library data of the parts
C81-C84 C106 = CMP-0006841-4: CAP, CERM, 100 pF, 50 V, +/- 5%, C0G/NP0, 0603; Manufacturer: Kemet; Polarized: N; Value: 100pF; U/M: EA; Value1: Unknown; VDC_V: 50V; TaMin_C: -55°C; TaMax_C: 125°C; Cap_Case: 0603; AEC Category: Q200; SizeArea_mm2: 1.28; SizeAreaWB_mm2: 4.68; SizeX_mm: 1.6; SizeY_mm: 0.8; SizeZ_mm: 1
C86 = CMP-0007100-4: CAP, CERM, 0.033 uF, 100 V, +/- 10%, X7S, AEC-Q200 Grade 1, 0603; Manufacturer: TDK; Polarized: N; U/M: EA; Cap_F: 33nF; ESR_ohm: 0.1396; Value1: 0.139637 ohm; VDC_V: 100V; IRMS_A: 462.257mA; TaMin_C: -55°C; TaMax_C: 125°C; Cap_Case: 0603; AEC Category: Q200; AEC Qualified: Y; AEC Grade: 1; SizeArea_mm2: 1.28; SizeAreaWB_mm2: 4.68; SizeX_mm: 1.6; SizeY_mm: 0.8
C87 = CMP-0006727-4: as C85 on sheet BMC112A_Interface
C88 C93 C97 = CMP-0007469-4: CAP, CERM, 0.1 uF, 100 V, +/- 10%, X7R, 0603; Manufacturer: MuRata; Polarized: N; Value: 0.1uF; U/M: EA; Cap_F: 100nF; Value1: Unknown; VDC_V: 100V; TaMin_C: -55°C; TaMax_C: 125°C; Cap_Case: 0603; AEC Category: Q200; SizeArea_mm2: 1.28; SizeAreaWB_mm2: 4.68; SizeX_mm: 1.6; SizeY_mm: 0.8; SizeZ_mm: 1
D9 D10 = CMP-0076911-2: Diode, Switching, 75 V, 0.25 A, SOD-323; Manufacturer: Micro Commercial Components; Value1: 0.25A; Io_A: 250mA; TJmax_C: 150°C; AEC Category: Q101; Green_Lifecycle: Not Set; Green_REACh: Incomplete; SizeArea_mm2: 3.645; SizeAreaWB_mm2: 8.695; SizeX_mm: 2.7; SizeY_mm: 1.35; SizeZ_mm: 1.0
D11 = CMP-0002894-2: LED, Green, SMD; Manufacturer: Wurth Elektronik; Type: AlInGaP; Vf_V: 2V; Io_A: 20mA; Value1: W
D12 = CMP-0002892-3: LED, Yellow, SMD; Manufacturer: Wurth Elektronik; Type: AlInGaP; Vf_V: 2V; Io_A: 20mA; Value1: W
J33 = CMP-0054794-2: as J16 on sheet BMC112A_Interface
J36 = CMP-0054796-4: as J28-J30 on sheet BMC112A_Interface
R73 R74 = CMP-0022204-4: RES, 20.0 k, 1%, 0.1 W, AEC-Q200 Grade 0, 0603; Manufacturer: Vishay-Dale; Value: 20.0k; Res_ohm: 20k; Value_Code: 20k0; Power_W: 100mW; Value2: 0.1W; VDC_V: 75V; TempCo: 100 ppm/C; EIA_Code: E96; SizeArea_mm2: 1.28; SizeX_mm: 1.6; SizeY_mm: 0.8; SizeZ_mm: 1; AEC Category: Q200; AEC Qualified: Y; AEC Grade: 0
R75 = CMP-0021283-3: RES, 49.9 k, 1%, 0.125 W, AEC-Q200 Grade 0, 0805; Manufacturer: Vishay-Dale; Value: 49.9k; Value_Code: 49k9; Power_W: 125mW; Value2: 0.125W; VDC_V: 150V; TempCo: 100 ppm/C; EIA_Code: E96; AEC Category: Q200; AEC Qualified: Y; AEC Grade: 0; SizeArea_mm2: 2.5; SizeX_mm: 2; SizeY_mm: 1.25; SizeZ_mm: 1.45
R76 = CMP-0021087-3: RES, 26.7 k, 1%, 0.125 W, AEC-Q200 Grade 0, 0805; Manufacturer: Vishay-Dale; Value: 26.7k; Value_Code: 26k7; Power_W: 125mW; Value2: 0.125W; VDC_V: 150V; TempCo: 100 ppm/C; EIA_Code: E96; AEC Category: Q200; AEC Qualified: Y; AEC Grade: 0; SizeArea_mm2: 2.5; SizeX_mm: 2; SizeY_mm: 1.25; SizeZ_mm: 1.45
R77 R78 = CMP-0021991-4: RES, 100, 1%, 0.1 W, AEC-Q200 Grade 0, 0603; Manufacturer: Vishay-Dale; Power_W: 100mW; TempCo: 100 ppm/C; Value_Code: 100R; Value: 100; EIA_Code: E96; SizeX_mm: 1.6; SizeY_mm: 0.8; SizeZ_mm: 1; Value2: 0.1W; SizeArea_mm2: 1.28; AEC Qualified: Y; VDC_V: 75V; AEC Category: Q200; AEC Grade: 0
R79 = CMP-0022270-4: RES, 2.10 k, 1%, 0.1 W, AEC-Q200 Grade 0, 0603; Manufacturer: Vishay-Dale; Value: 2.10k; Res_ohm: 2.1k; Value_Code: 2k10; Power_W: 100mW; Value2: 0.1W; VDC_V: 75V; TempCo: 100 ppm/C; EIA_Code: E96; AEC Category: Q200; AEC Qualified: Y; AEC Grade: 0; SizeArea_mm2: 1.28; SizeX_mm: 1.6; SizeY_mm: 0.8; SizeZ_mm: 1
R80 = CMP-0022453-4: RES, 4.42 k, 1%, 0.1 W, AEC-Q200 Grade 0, 0603; Manufacturer: Vishay-Dale; Value: 4.42k; Value_Code: 4k42; Power_W: 100mW; Value2: 0.1W; VDC_V: 75V; TempCo: 100 ppm/C; EIA_Code: E96; AEC Category: Q200; AEC Qualified: Y; AEC Grade: 0; SizeArea_mm2: 1.28; SizeX_mm: 1.6; SizeY_mm: 0.8; SizeZ_mm: 1
R81 = CMP-0022109-5: RES, 1.00 k, 1%, 0.1 W, AEC-Q200 Grade 0, 0603; Manufacturer: Vishay-Dale; Value: 1.00k; Res_ohm: 1k; Value_Code: 1k00; Power_W: 100mW; Value2: 0.1W; VDC_V: 75V; TempCo: 100 ppm/C; EIA_Code: E96; AEC Category: Q200; AEC Grade: 0; AEC Qualified: Y; SizeArea_mm2: 1.28; SizeX_mm: 1.6; SizeY_mm: 0.8; SizeZ_mm: 1
R83 = CMP-0023267-5: RES, 75.0 k, 1%, 0.1 W, 0603; Manufacturer: Yageo; Res_ohm: 75k; Power_W: 100mW; VDC_V: 75V; TempCo: 100 ppm/C; AEC Qualified: N; SizeZ_mm: 1; Value_Code: 75k0; Value: 75.0k; EIA_Code: E96; SizeX_mm: 1.6; SizeY_mm: 0.8; Value2: 0.1W; SizeArea_mm2: 1.28; AEC Category: Q200; SizeAreaWB_mm2: 4.68
R84 = CMP-0022237-4: RES, 24.9 k, 1%, 0.1 W, AEC-Q200 Grade 0, 0603; Manufacturer: Vishay-Dale; Power_W: 100mW; TempCo: 100 ppm/C; Value_Code: 24k9; Value: 24.9k; EIA_Code: E96; SizeX_mm: 1.6; SizeY_mm: 0.8; SizeZ_mm: 1; Value2: 0.1W; SizeArea_mm2: 1.28; AEC Qualified: Y; VDC_V: 75V; AEC Category: Q200; AEC Grade: 0
R85 R92 = CMP-0022109-5: RES, 1.00 k, 1%, 0.1 W, AEC-Q200 Grade 0, 0603; Manufacturer: Vishay-Dale; Value: 1.00k; Res_ohm: 1k; Value_Code: 1k00; Power_W: 100mW; Value2: 0.1W; VDC_V: 75V; TempCo: 100 ppm/C; EIA_Code: E96; SizeX_mm: 1.6; SizeY_mm: 0.8; SizeZ_mm: 1; SizeArea_mm2: 1.28; AEC Qualified: Y; AEC Category: Q200; AEC Grade: 0
R86 = CMP-0022449-4: RES, 4.02 k, 1%, 0.1 W, AEC-Q200 Grade 0, 0603; Manufacturer: Vishay-Dale; Power_W: 100mW; TempCo: 100 ppm/C; Value_Code: 4k02; Value: 4.02k; EIA_Code: E96; SizeX_mm: 1.6; SizeY_mm: 0.8; SizeZ_mm: 1; Value2: 0.1W; SizeArea_mm2: 1.28; AEC Qualified: Y; VDC_V: 75V; AEC Category: Q200; AEC Grade: 0
R90 R91 = CMP-0022458-4: RES, 4.99 k, 1%, 0.1 W, AEC-Q200 Grade 0, 0603; Manufacturer: Vishay-Dale; Value: 4.99k; Value_Code: 4k99; Power_W: 100mW; Value2: 0.1W; VDC_V: 75V; TempCo: 100 ppm/C; EIA_Code: E96; AEC Category: Q200; AEC Grade: 0; AEC Qualified: Y; SizeArea_mm2: 1.28; SizeX_mm: 1.6; SizeY_mm: 0.8; SizeZ_mm: 1
R110 = CMP-0020448-3: RES, 10, 5%, 0.125 W, AEC-Q200 Grade 0, 0805; Manufacturer: Vishay-Dale; Power_W: 125mW; TempCo: 200 ppm/C; Value_Code: 10R0; Value: 10; EIA_Code: E24; SizeX_mm: 2; SizeY_mm: 1.25; SizeZ_mm: 1.45; Value2: 0.125W; SizeArea_mm2: 2.5; AEC Qualified: Y; VDC_V: 150V; AEC Category: Q200; AEC Grade: 0
TP1-TP4 = CMP-0067619-1: Natural PC Test Point Brass, SMT; Manufacturer: Harwin
U4 = CMP-0051649-3: Automotive Catalog Single Inverter, DBV0005A, LARGE T&R; Manufacturer: Texas Instruments; Generic Part Number: SN74LVC1G04-Q1; CompType: IC; 3-State Output: No; AEC Category: Q200; AEC Qualified: Y; Bits(#): 1; F @ Nom Voltage(Max)(Mhz): 150; Green_Lifecycle: Active; Green_REACh: Passed; ICC @ Nom Voltage(Max)(mA): 0.01; Input Type: CMOS/TTL; Logic: Inverting; Output Drive (IOL/IOH)(Max)(mA): 32/-32; Output Type: CMOS; SizeArea_mm2: 8.12; SizeAreaWB_mm2: 14.82; SizeX_mm: 2.8; SizeY_mm: 2.9; SizeZ_mm: 1.45; Technology Family: LVC; tpd @ Nom Voltage(Max)(ns): 7.5,5.2,4.2,3.7; VCC(Max)(V): 5.5; VCC(Min)(V): 1.65; Voltage(Nom)(V): 1.8,2.5,3.3,5

## Sheet BMC112A_Hardware.SchDoc: LM5171 EVM Hardware Page
size 431 x 279 mm; Date: Not shown in title block; ApprovedBy: Not shown in title block; CheckedBy: Not shown in title block; Author: Not shown in title block; CompanyName: Not shown in title block; Engineer: Not shown in title block; Organization: Not shown in title block; Address1: Not shown in title block; Address2: Not shown in title block; Address3: Not shown in title block; Address4: Not shown in title block; DocumentNumber: 8; Revision: Use project parameter SCH_Rev; SheetNumber: 8; SheetTotal: 8; PageSetup: Record=PageOptions¦CenterHorizontal=True¦CenterVertical=True¦PrintScale=1.00¦XCorrection=1.00¦YCorrection=1.00¦PrintKind=0¦BorderSize=5000000¦LeftOffset=0¦BottomOffset=0¦Orientation=2¦PaperLength=1000¦PaperWidth=1000¦Scale=100¦PaperSource=15¦PrintQuality=600¦MediaType=1¦DitherType=10¦PaperKind=Letter¦PrintScaleMode=1
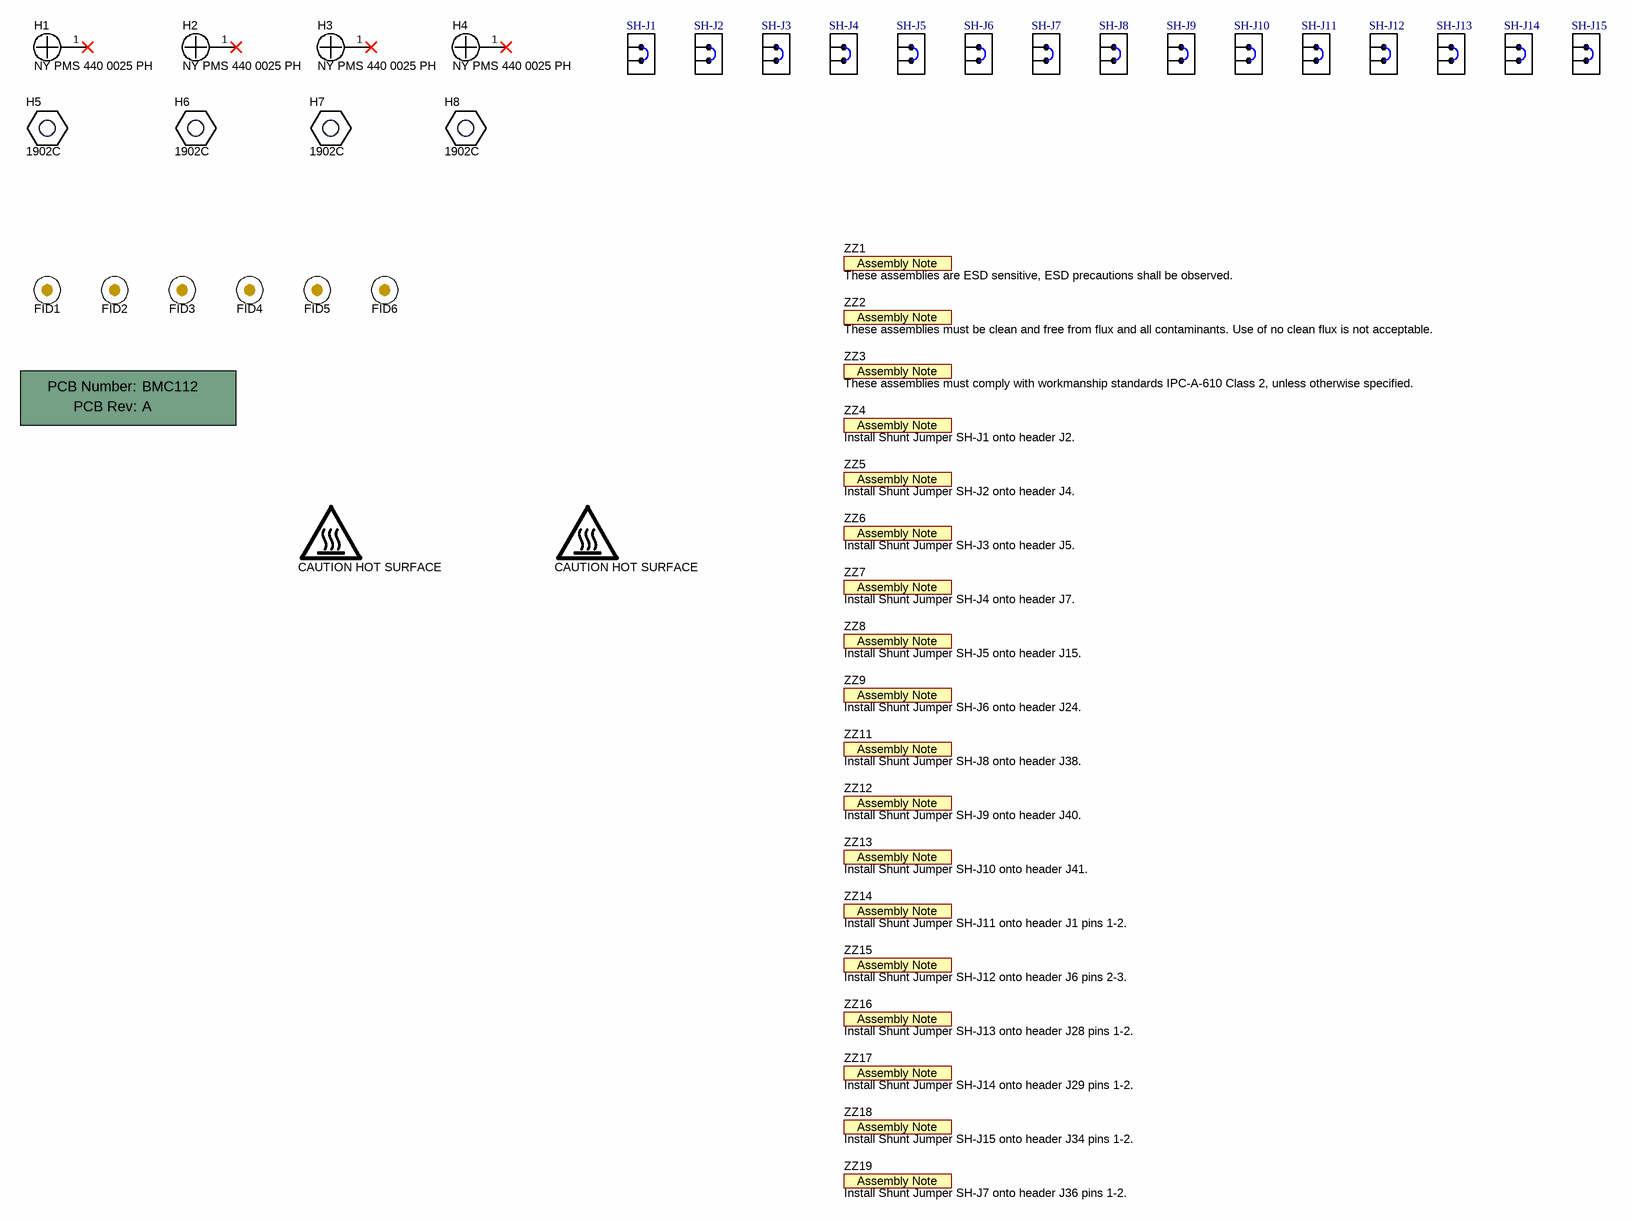
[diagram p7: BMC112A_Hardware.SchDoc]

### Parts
!PCB  Printed Circuit Board  (value not drawn)  (mechanical)
FID1  Fiducial  [Fiducial10-20]  (value not drawn)
FID2  Fiducial  [Fiducial10-20]  (value not drawn)
FID3  Fiducial  [Fiducial10-20]  (value not drawn)
FID4  Fiducial  [Fiducial10-20]  (value not drawn)
FID5  Fiducial  [Fiducial10-20]  (value not drawn)
FID6  Fiducial  [Fiducial10-20]  (value not drawn)
H1  NY PMS 440 0025 PH  [NY PMS 440 0025 PH]
H2  NY PMS 440 0025 PH  [NY PMS 440 0025 PH]
H3  NY PMS 440 0025 PH  [NY PMS 440 0025 PH]
H4  NY PMS 440 0025 PH  [NY PMS 440 0025 PH]
H5  1902C  [Keystone_1902C]
H6  1902C  [Keystone_1902C]
H7  1902C  [Keystone_1902C]
H8  1902C  [Keystone_1902C]
Logo5  CAUTION HOT SURFACE  [IEC_HotSurface_Small]  (no BOM)
Logo6  CAUTION HOT SURFACE  [IEC_HotSurface_Small]  (no BOM)
SH-J1  M7582-05  [Harwin_M7582-05]  (value not drawn)
SH-J2  M7582-05  [Harwin_M7582-05]  (value not drawn)
SH-J3  M7582-05  [Harwin_M7582-05]  (value not drawn)
SH-J4  M7582-05  [Harwin_M7582-05]  (value not drawn)
SH-J5  M7582-05  [Harwin_M7582-05]  (value not drawn)
SH-J6  M7582-05  [Harwin_M7582-05]  (value not drawn)
SH-J7  M7582-05  [Harwin_M7582-05]  (value not drawn)
SH-J8  M7582-05  [Harwin_M7582-05]  (value not drawn)
SH-J9  M7582-05  [Harwin_M7582-05]  (value not drawn)
SH-J10  M7582-05  [Harwin_M7582-05]  (value not drawn)
SH-J11  M7582-05  [Harwin_M7582-05]  (value not drawn)
SH-J12  M7582-05  [Harwin_M7582-05]  (value not drawn)
SH-J13  M7582-05  [Harwin_M7582-05]  (value not drawn)
SH-J14  M7582-05  [Harwin_M7582-05]  (value not drawn)
SH-J15  M7582-05  [Harwin_M7582-05]  (value not drawn)
ZZ1  These assemblies are ESD sensitive, ESD precautions shall be observed.  [AssemblyNote]  (no BOM)
ZZ2  These assemblies must be clean and free from flux and all contaminants. Use of no clean flux is not acceptable.  [AssemblyNote]  (no BOM)
ZZ3  These assemblies must comply with workmanship standards IPC-A-610 Class 2, unless otherwise specified.  [AssemblyNote]  (no BOM)
ZZ4  Install Shunt Jumper SH-J1 onto header J2.  [AssemblyNote]  (no BOM)
ZZ5  Install Shunt Jumper SH-J2 onto header J4.  [AssemblyNote]  (no BOM)
ZZ6  Install Shunt Jumper SH-J3 onto header J5.  [AssemblyNote]  (no BOM)
ZZ7  Install Shunt Jumper SH-J4 onto header J7.  [AssemblyNote]  (no BOM)
ZZ8  Install Shunt Jumper SH-J5 onto header J15.  [AssemblyNote]  (no BOM)
ZZ9  Install Shunt Jumper SH-J6 onto header J24.  [AssemblyNote]  (no BOM)
ZZ11  Install Shunt Jumper SH-J8 onto header J38.  [AssemblyNote]  (no BOM)
ZZ12  Install Shunt Jumper SH-J9 onto header J40.  [AssemblyNote]  (no BOM)
ZZ13  Install Shunt Jumper SH-J10 onto header J41.  [AssemblyNote]  (no BOM)
ZZ14  Install Shunt Jumper SH-J11 onto header J1 pins 1-2.  [AssemblyNote]  (no BOM)
ZZ15  Install Shunt Jumper SH-J12 onto header J6 pins 2-3.  [AssemblyNote]  (no BOM)
ZZ16  Install Shunt Jumper SH-J13 onto header J28 pins 1-2.  [AssemblyNote]  (no BOM)
ZZ17  Install Shunt Jumper SH-J14 onto header J29 pins 1-2.  [AssemblyNote]  (no BOM)
ZZ18  Install Shunt Jumper SH-J15 onto header J34 pins 1-2.  [AssemblyNote]  (no BOM)
ZZ19  Install Shunt Jumper SH-J7 onto header J36 pins 1-2.  [AssemblyNote]  (no BOM)

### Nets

Not connected (* = marked no-connect by the designer): H1 1*; H2 1*; H3 1*; H4 1*

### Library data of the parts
!PCB = CMP-0003618-2: Manufacturer: Any; PartNumber: BMC112
FID1-FID6 = CMP-0077181-1: Fiducial mark.  There is nothing to buy or mount.
H1-H4 = CMP-0003617-1: Machine Screw, Round, #4-40 x 1/4, Nylon, Philips panhead; Manufacturer: B&F Fastener Supply; CompType: Hardware
H5-H8 = CMP-0003610-1: Standoff, Hex, 0.5"L #4-40 Nylon; Manufacturer: Keystone; CompType: Hardware
Logo5 Logo6 = CMP-0074837-2: IEC 61010-1 Hot Surface Warning; Manufacturer: Texas Instruments; CompType: IC; AEC Category: Q200; SymbolCreator: a0412235
SH-J1-SH-J15 = CMP-0078738-1: Single Operation 2.54mm Pitch Open Top Jumper Socket; Manufacturer: Harwin
ZZ1 = CMP-0077236-1
ZZ2 = CMP-0077237-1
ZZ3 = CMP-0077238-1
ZZ4-ZZ9 ZZ11-ZZ19 = CMP-0077238-1: These assemblies must comply with workmanship standards IPC-A-610 Class 2, unless otherwise specified.

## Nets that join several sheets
AGND: BMC112A_OVP (27 pins), BMC112A_Controller (49 pins), BMC112A_Interface (66 pins), BMC112A_Analog (10 pins)
PGND: BMC112A_Bias (19 pins), BMC112A_Controller (5 pins), BMC112A_Power (49 pins), BMC112A_Interface (J17.37 J18.37)
V5.0: BMC112A_OVP (13 pins), BMC112A_Controller (C15.1 R15.2 R108.2 U1.12), BMC112A_Interface (J17.25 R42.2 R105.2), BMC112A_Analog (R110.2)
V10: BMC112A_Bias (C80.1 D6.1 R61.2 R68.1), BMC112A_Controller (5 pins), BMC112A_Interface (J17.43 J19.2)
V12: BMC112A_Controller (C4.1 J1.3 R45.2), BMC112A_Power (17 pins), BMC112A_Analog (R78.1 TP4.1)
V48: BMC112A_Bias (D7.2 J41.2), BMC112A_OVP (R88.2), BMC112A_Controller (C6.1 J1.1 U1.13 U1.24), BMC112A_Power (28 pins), BMC112A_Analog (R77.2 TP1.1)
VREF: BMC112A_OVP (R89.1), BMC112A_Controller (C75.1 R11.2 R46.1 U1.1)
CSA1: BMC112A_Controller (C7.1 C8.1 U1.32), BMC112A_Power (R56.1), BMC112A_Interface (R96.1)
CSA2: BMC112A_Controller (C34.1 C36.2 U1.5), BMC112A_Power (R58.1), BMC112A_Interface (R98.1)
CSB1: BMC112A_Controller (C7.2 C9.1 U1.31), BMC112A_Power (R57.1), BMC112A_Interface (R97.1)
CSB2: BMC112A_Controller (C30.1 C36.1 U1.6), BMC112A_Power (R59.1), BMC112A_Interface (R99.1)
DEM: BMC112A_Controller (Q5.1 Q6.1 R12.2), BMC112A_Interface (J17.23 J18.23)
DIR: BMC112A_Controller (U1.11 U1.26), BMC112A_Interface (J17.9 J18.9 J28.2), BMC112A_Analog (U4.2)
EN1: BMC112A_Controller (J24.1 U1.27), BMC112A_Interface (J17.7 J23.1 J29.2)
EN2: BMC112A_Controller (J24.2 U1.10), BMC112A_Interface (J17.21 J30.2)
ERRHV: BMC112A_Controller (U1.34), BMC112A_Analog (C83.1 C86.1 D9.2)
ERRLV: BMC112A_Controller (U1.3), BMC112A_Analog (C84.2 C87.1 D10.2)
FBHV: BMC112A_Controller (U1.35), BMC112A_Analog (5 pins)
FBLV: BMC112A_Controller (U1.2), BMC112A_Analog (5 pins)
HO1: BMC112A_Controller (U1.22), BMC112A_Power (R22.1 R30.1)
HO2: BMC112A_Controller (U1.15), BMC112A_Power (R37.1 R41.1)
IOUT1: BMC112A_Controller (J2.2 J21.1 U1.33), BMC112A_Interface (J16.1 J17.27)
IOUT2: BMC112A_Controller (J7.1 J21.2 U1.4), BMC112A_Interface (J17.29)
ISETA: BMC112A_OVP (J42.2), BMC112A_Controller (U1.7 U1.30), BMC112A_Interface (J17.11 J18.11), BMC112A_Analog (J36.2)
ISETD: BMC112A_Interface (J17.13 J18.13), BMC112A_Analog (J33.1 R92.1)
LDODRV: BMC112A_Bias (R71.2), BMC112A_Controller (U1.25)
LO1: BMC112A_Controller (U1.20), BMC112A_Power (R27.1 R28.1)
LO2: BMC112A_Controller (U1.17), BMC112A_Power (R38.1 R39.1)
OPT: BMC112A_Controller (J6.2 U1.41), BMC112A_Interface (J17.19 J18.19 J32.2)
OTEMP: BMC112A_OVP (6 pins), BMC112A_Controller (D3.1), BMC112A_Interface (D5.1)
SCL: BMC112A_Controller (U1.38), BMC112A_Interface (J17.41 J18.41 J25.2 J31.9)
SD_CMD: BMC112A_Controller (Q7.1 R5.2), BMC112A_Interface (J17.45 J20.2)
SDA: BMC112A_Controller (U1.37), BMC112A_Interface (J17.39 J18.39 J31.10 J44.2)
SS/DEM1: BMC112A_OVP (U3.4), BMC112A_Controller (5 pins)
SW1: BMC112A_Controller (C11.2 U1.21), BMC112A_Power (8 pins)
SW2: BMC112A_Controller (C17.2 U1.16), BMC112A_Power (8 pins)
SYNCIN: BMC112A_Controller (U1.40), BMC112A_Interface (J17.15)
SYNCOUT: BMC112A_Controller (J27.2 U1.39), BMC112A_Interface (J13.1 J17.17)
UVLO: BMC112A_Bias (J40.1), BMC112A_Controller (D8.1 R2.1 R6.2 R7.2), BMC112A_Interface (J17.5 J22.1)
V12SNS: BMC112A_Controller (C38.1 R45.1 R49.2 U1.36), BMC112A_Interface (J17.3)
V48SNS: BMC112A_OVP (C96.1 R88.1 R100.2 U3.1), BMC112A_Interface (J17.1)

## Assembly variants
001: not fitted C7 C8 C9 C30 C34 C36 C81 C82 CS1A CS1B CS2A CS2B J27 R6 R73 R74 R104 R108 TP1 TP2 TP3 TP4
